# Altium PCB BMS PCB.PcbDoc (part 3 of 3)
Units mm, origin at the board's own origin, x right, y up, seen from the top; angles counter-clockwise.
Board outline 105 x 42 mm, 6 copper layers (TOP, GND TOP, IN, GND IN, GND BOT, BOT), stack 1.517 mm thick; 241 components, 153 nets, 670 pads, 889 vias.
Unrouted connection lines stored in the file: 76.
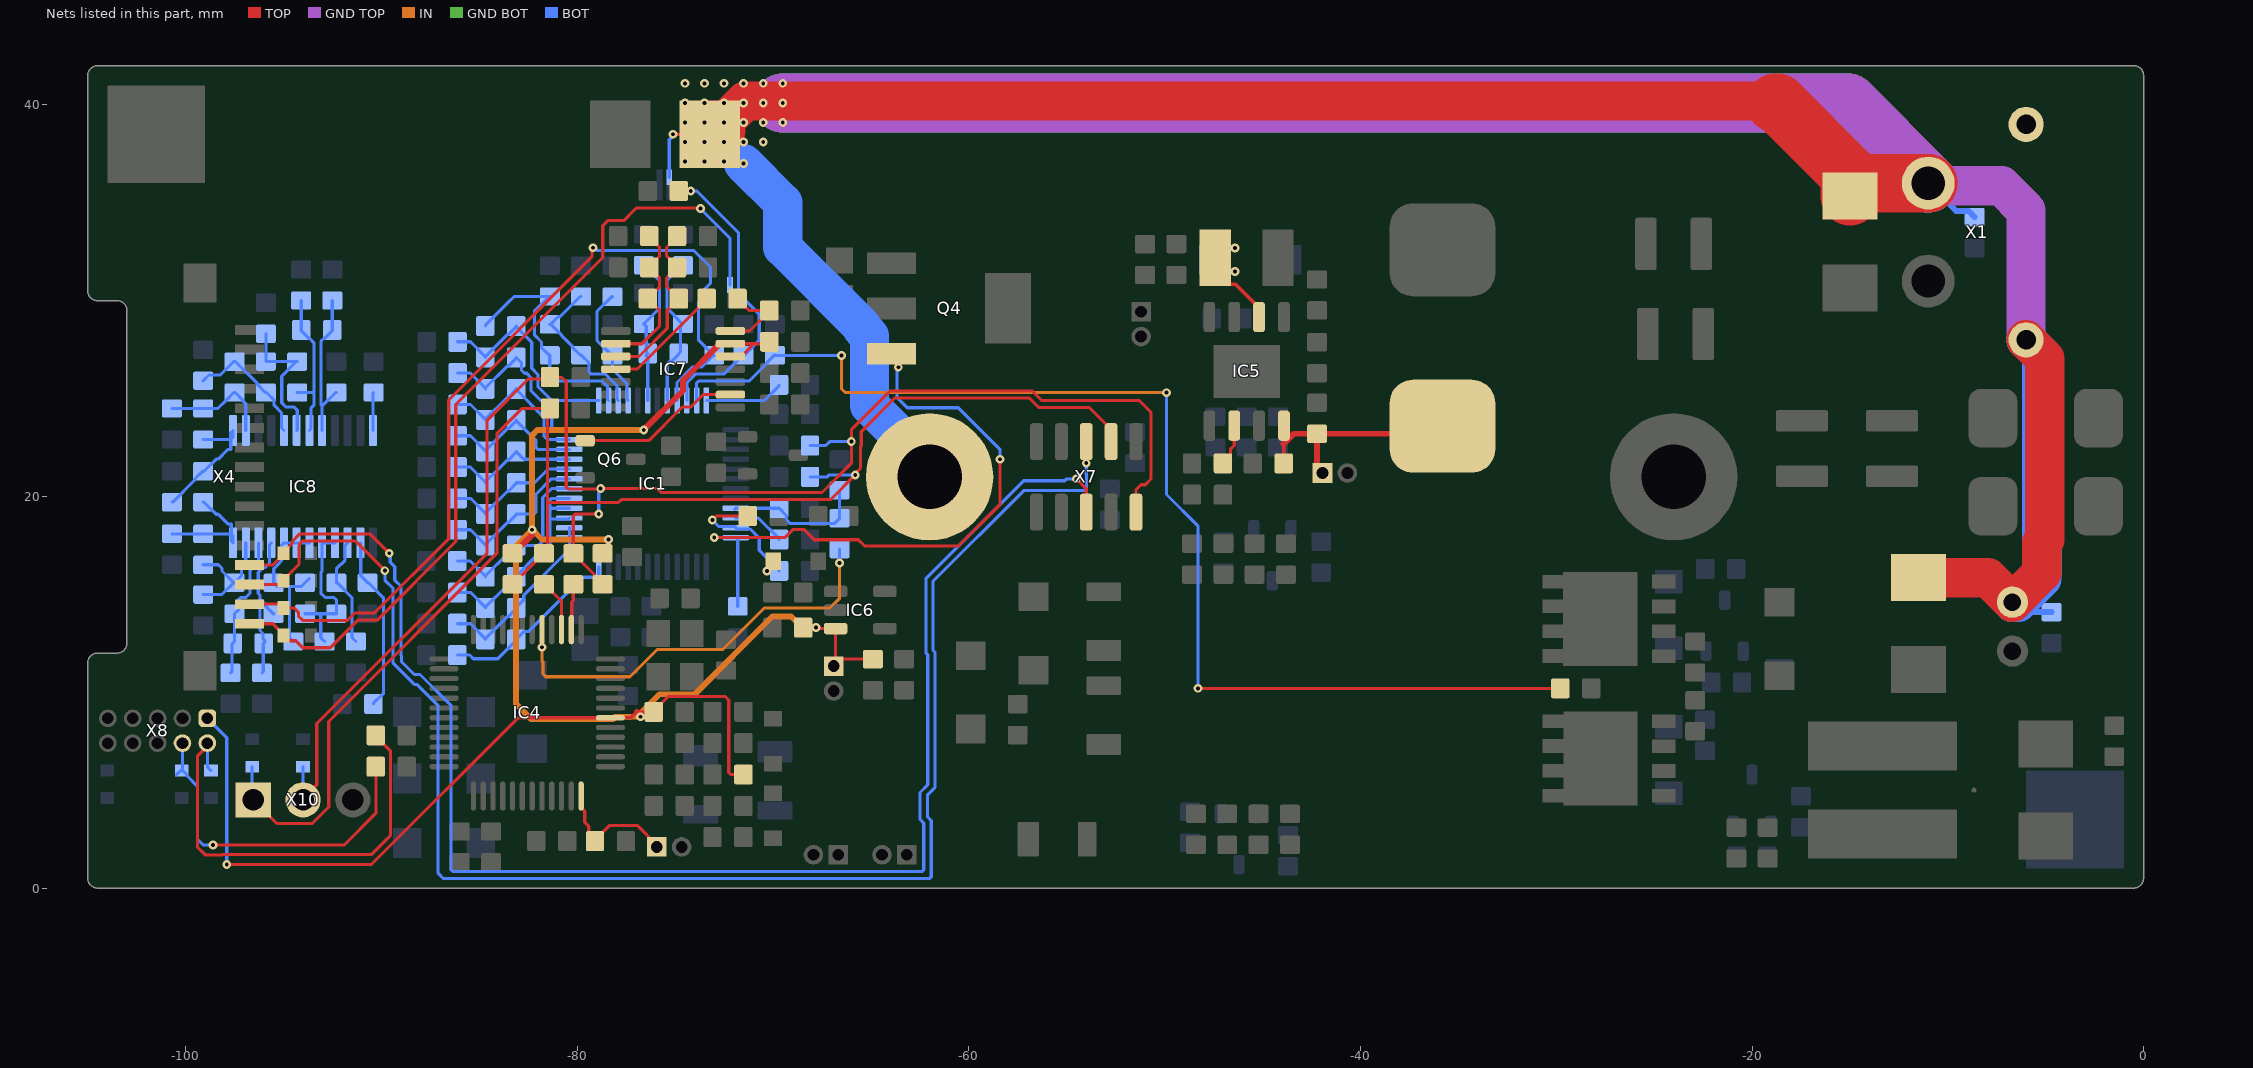
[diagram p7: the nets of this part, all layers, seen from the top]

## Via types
v1: diameter 0.45, hole 0.2, TOP to BOT, tented both sides, 886 vias
v2: diameter 0.45/0.45/0.45/0.45/0.45/0 (per signal layer), hole 0.2, TOP to BOT, tented both sides, 3 vias

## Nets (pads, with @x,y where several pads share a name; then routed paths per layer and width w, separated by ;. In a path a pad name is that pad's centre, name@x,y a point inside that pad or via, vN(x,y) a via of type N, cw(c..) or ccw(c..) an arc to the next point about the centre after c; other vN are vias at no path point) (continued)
PACK-: C38.1 C39.1 D27.A D28.A MH2.1 NT2.1 R1.2 X1.- X1.CASE X2.2 | length 325.7
  TOP w0.16: v1(-75.1,38.5) R1.2@-73.228,38.5
  TOP w0.3: D27.A@-16.25,34.3 -15,35.55 D27.A@-14.8,35.55 ; D28.A@-11.7,15.85 D28.A@-11.5,15.85
  TOP w2: R1.2@-72.893,38.728 -71.421,40.2 -18.9,40.2 -18.8,40.1 ; D28.A@-11.5,15.85 -7.95,15.85 X2.2@-6.7,14.6 -5.2,16.1 -5.2,17.636 -5.05,17.786 -5.05,27.05 X1.CASE@-6,28
  TOP w3: R1.2@-73.228,38.5 -73.228,38.678 -73.178,38.728 R1.2@-72.893,38.728 ; -18.8,40.1 -18.7,40.1 -15,36.4 D27.A@-15,35.35 -14.35,36 X1.-@-11,36
  GND TOP w2: X1.-@-11,36 -10.866,35.866 -7.266,35.866 -6,34.6 X1.CASE@-6,28
  GND TOP w3: v1(-69.5,40.1) -15.1,40.1 X1.-@-11,36
  GND BOT w3: v1(-69.5,40.1) -15.1,40.1 X1.-@-11,36
  BOT w0.16: NT2.1@-75.3,36.3 -75.3,38.222 -75.1,38.422 v1(-75.1,38.5)
  BOT w0.3: X1.-@-11,36 -9.585,34.585 -8.945,34.585 C38.1@-8.625,34.265 ; X2.2@-6.417,14.6 -6.348,14.6 -5.838,14.09 C39.1@-4.7,14.09
  BOT w2: v1(-73.5,38.1) -73.4,38.1 -73,38.5 v1@-72.5,38 ; v1(-71.5,37) -69.5,35 -69.5,32.727 -65.449,28.676 -65.449,28.578 -65.075,28.203 -65.075,24.659 -62,21.584 MH2.1@-62,21 ; X2.2@-6.7,14.6 -6.417,14.6 -5.2,15.817 -5.2,27.2 X1.CASE@-6,28
  BOT w3: v1(-69.5,40.1) -15.1,40.1 X1.-@-11,36
  other v1: -74.5,37.1 -73.5,37.1 -72.5,37.1 -74.5,38.1 -72.5,38.1 -71.5,38.1 -70.5,38.1 -74.5,39.1 -73.5,39.1 -72.5,39.1 -71.5,39.1 -70.5,39.1 -69.5,39.1 -74.5,40.1 -73.5,40.1 -72.5,40.1 -71.5,40.1 -70.5,40.1 -74.5,41.1 -73.5,41.1 -72.5,41.1 -71.5,41.1 -70.5,41.1 -69.5,41.1
PGOOD: D30.K IC5.6 | length 2.2
  TOP w0.16: D30.K@-47.02,21.69 -46.639,22.071 -46.639,22.409 -46.445,22.603 IC5.6@-46.445,23.618
REG1: C15.2 D6.A D43.A IC1.35 | length 6.8
  TOP w0.16: v1(-73.1,18.8) -72.9,19 D43.A@-71.29,19
  BOT w0.16: v1(-73.1,18.8) -72.76,18.46 -71.96,18.46 IC1.35@-71.9,18.4 -71.84,18.34 -71.17,18.34 -70.7,17.87 -70.7,17.25 -69.69,16.24 C15.2@-69.69,16.2
  other v1: -70.3,16.2
REG2: C14.2 IC1.34 | length 2.7
  BOT w0.16: IC1.34@-71.9,18.9 -70.75,18.9 -69.69,17.84 C14.2@-69.69,17.8
REG18: C24.2 IC1.24 | length 4.1
  BOT w0.16: IC1.24@-73.4,24.9 -70.443,24.899 -69.69,25.652 C24.2@-69.69,25.7
REG25: C48.2 IC7.7 R76.2 | length 4.3
  TOP w0.16: IC7.7@-72.175,28.45 -71.2,28.45 -70.19,29.46 C48.2@-70.19,29.5 -71.21,29.5 -71.389,29.679 -71.421,29.679 -71.81,30.068 R76.2@-71.81,30.1
REGIN: C12.2 IC1.36 Q4.E | length 32.2
  TOP w0.16: v1(-73,17.9) -69.4,17.9 -68.995,18.305 -68.405,18.305 -67.89,17.79 -65.642,17.79 -65.322,17.47 -60.538,17.47 -58.4,19.608 v1(-58.4,21.9) ; Q4.E@-63.94,27.3 -63.6,26.96 v1(-63.6,26.6)
  BOT w0.16: v1(-73,17.9) IC1.36@-71.9,17.9 -71.86,17.9 -71.8,17.84 C12.2@-71.8,14.39 ; v1(-63.6,26.6) -63.655,26.545 -63.655,26.38 -63.675,26.361 -63.675,25.069 -63.135,24.53 -60.538,24.53 -58.4,22.392 v1(-58.4,21.9)
RST/SHUT: IC4.17 R32.2 | length 21.7
  TOP w0.16: v1(-81.8,12.3) IC4.17@-81.8,13.2
  IN w0.16: v1(-81.8,12.3) -81.8,11.608 -81.74,11.548 -81.74,10.934 -81.601,10.795 -77.305,10.795 -75.915,12.185 -72.565,12.185 -70.445,14.305 -67.095,14.305 -66.6,14.8 v1(-66.6,16.6)
  BOT w0.16: v1(-66.6,16.6) R32.2@-66.6,17.31
"RST/SHUT BMS": C25.2 IC1.33 R32.1 R34.2 | length 7.4
  BOT w0.16: IC1.33@-71.96,19.34 IC1.33@-71.9,19.4 C25.2@-69.69,19.4 -69.309,19.019 -69.309,18.802 -69.116,18.61 -66.88,18.61 R32.1@-66.6,18.89 R34.2@-66.6,20.31
"SCL MCU": IC4.14 R47.2 | length 2.4
  TOP w0.16: IC4.14@-80.3,13.2 -80.279,13.221 -80.279,14.61 -80.201,14.689 R47.2@-80.2,15.51
SCLt: D5.K R29.2 R45.1 R47.1 R73.2 X7.9 X10.2 | length 84.1
  TOP w0.16: X10.2@-94,4.5 -94,4.58 -93.3,5.28 -93.3,8.406 -84.6,17.106 -84.6,23.9 -82.5,26 -81.49,26 R73.2@-81.39,26.1 -81.364,26.074 -80.774,26.074 -80.56,25.86 -80.56,20.472 -80.466,20.379 -78.821,20.379 v1(-78.8,20.4) -75.911,20.4 -75.711,20.2 -67.5,20.2 -66,21.7 v1(-66,22.8) -66,23.4 -64.01,25.39 -56.773,25.39 -56.283,24.9 -51.286,24.9 -50.7,24.314 -50.7,21.314 -50.695,21.309 -50.695,20.891 -50.991,20.595 -51.205,20.595 -51.46,20.34 X7.9@-51.46,19.2 ; R47.1@-80.56,17.45 R47.1@-80.2,17.09 -80.2,19.006 -80.106,19.1 v1(-78.9,19.1) ; R47.1@-80.168,17.09 -79.779,16.701 -79.779,16.669 -79.121,16.011 -79.121,15.899 -78.732,15.51 R45.1@-78.7,15.51
  BOT w0.16: X10.2@-94,4.5 D5.K@-94,6.2 ; v1(-78.9,19.1) -78.9,20.222 -78.8,20.322 v1(-78.8,20.4) ; R29.2@-68.11,22.6 -67.3,22.6 -67.1,22.8 v1(-66,22.8)
"SDA MCU": IC4.15 R48.2 | length 2.7
  TOP w0.16: R48.2@-81.7,15.51 -81.66,15.51 -80.8,14.65 IC4.15@-80.8,13.2
SDAt: D4.K R27.2 R46.1 R48.1 R71.2 X7.8 X10.1 | length 77.9
  TOP w0.16: X10.1@-96.54,4.5 -95.34,3.3 -93.531,3.3 -92.688,4.143 -92.688,8.509 -84.1,17.097 -84.1,23.2 -82.8,24.5 R71.2@-81.39,24.5 -81.525,24.365 -81.525,19.7 ; R46.1@-83.3,15.51 -83.268,15.51 -82.879,15.899 -82.879,15.931 -82.121,16.689 -82.121,16.701 -81.733,17.09 R48.1@-81.7,17.09 -81.7,17.3 -81.525,17.475 -81.525,19.7 ; X7.8@-52.73,22.8 -52.73,23.42 -53.85,24.54 -56.432,24.54 -56.922,25.03 -63.778,25.03 -65.495,23.313 -65.495,22.591 -65.53,22.556 -65.53,21.448 -65.8,21.178 v1(-65.8,21.1) -67.06,19.84 -77.746,19.84 -77.891,19.695 -78.309,19.695 -78.314,19.7 -81.525,19.7
  BOT w0.16: D4.K@-96.6,6.2 -96.6,4.56 X10.1@-96.54,4.5 ; R27.2@-68.11,21 -67.231,21 -67.131,21.1 v1(-65.8,21.1)
SRN: C28.2 C30.2 IC1.20 R37.2 | length 8
  BOT w0.16: IC1.20@-75.4,24.9 -75.4,26.776 -75.298,26.879 -75.199,26.879 -74.81,27.267 C28.2@-74.81,27.3 -74.725,27.385 -74.725,28.685 C30.2@-74.6,28.81 -74.632,28.81 -75.021,29.199 -75.021,29.231 -75.409,29.619 -75.409,31.044 -75.315,31.137 -75.31,31.137 -74.647,31.8 R37.2@-74.6,31.8
"SRN FG": C49.2 C51.2 IC7.10 R75.2 | length 9.2
  TOP w0.16: IC7.10@-78.025,27.15 -76.841,27.15 -75.4,28.591 -75.4,29.51 -75.231,29.679 -75.199,29.679 -74.81,30.068 -74.81,30.132 -75.199,30.521 -75.231,30.521 -75.44,30.73 -75.44,31.16 -75.321,31.279 -75.289,31.279 -74.9,31.668 -74.9,31.748 -75.44,32.288 -75.44,32.712 -74.9,33.252 R75.2@-74.9,33.3
SRP: C28.1 C29.1 IC1.18 R36.2 | length 7.7
  BOT w0.16: R36.2@-76.6,31.81 -75.8,31.01 -75.8,29.61 C29.1@-76.6,28.81 -76.475,28.685 -76.475,27.385 C28.1@-76.39,27.3 -76.49,27.2 -76.4,27.11 IC1.18@-76.4,24.9
"SRP FG": C49.1 C50.1 IC7.9 R74.2 | length 8.4
  TOP w0.16: IC7.9@-78.025,27.8 -76.7,27.8 -75.8,28.7 -75.8,29.51 -75.969,29.679 -76.001,29.679 -76.39,30.068 -76.39,30.132 -76.001,30.521 -75.969,30.521 -75.8,30.69 -75.8,31.176 -75.902,31.279 -75.931,31.279 C50.1@-76.32,31.668 ; C50.1@-76.32,31.7 -76.32,31.748 -75.8,32.268 -75.8,32.732 -76.32,33.252 R74.2@-76.32,33.3
"SW 5V1": C40.2 IC5.8 L2.1 R62.1 X11.1 | length 13.5
  TOP w0.16: -43.92,22.68 C40.2@-43.92,21.73 ; IC5.8@-43.905,23.618 -43.905,22.695 C40.2@-43.905,21.745 ; C40.2@-43.92,21.73 C40.2@-43.92,21.69 -43.905,21.705 C40.2@-43.905,21.745 ; C40.2@-43.92,21.73 C40.2@-43.905,21.745
  TOP w0.3: -43.92,22.68 -43.905,22.695 -43.4,23.2 R62.1@-42.21,23.2 ; X11.1@-41.935,21.2 -42.21,21.475 R62.1@-42.21,23.2 ; L2.1@-35.81,23.59 -36.2,23.2 R62.1@-42.21,23.2
SWCLK: D2.K R50.2 X8.4 | length 17.9
  TOP w0.16: v1(-98.6,2.2) -91.9,2.2 -90.28,3.82 -90.28,6.19 R50.2@-90.29,6.2
  BOT w0.16: D2.K@-100.47,5.78 -100.25,6 D2.K@-100.2,6 ; X8.4@-100.16,7.4 -100.16,6.04 D2.K@-100.2,6 ; v1(-98.6,2.2) -99.1,2.2 -99.4,2.5 -99.4,5.2 -99.93,5.73 -99.93,5.78 -100.15,6 D2.K@-100.2,6
SWDIO: D1.K R49.2 X8.2 | length 23
  TOP w0.16: X8.2@-98.89,7.4 -98.89,7.246 -99.4,6.736 -99.4,2.1 -98.995,1.695 -98.119,1.695 -98.109,1.705 -90.515,1.705 -89.54,2.68 -89.54,7.01 -90.29,7.76 R49.2@-90.29,7.8
  BOT w0.16: X8.2@-98.814,7.476 X8.2@-98.89,7.4 -98.89,6.19 D1.K@-98.7,6
TS1: C20.2 D35.A IC1.21 X4.15 | length 45.1
  TOP w0.16: X4.15@-96.737,14.5 -95.2,14.5 D35.A@-95,14.3 -94.46,14.3 -94.238,14.078 -94.238,13.892 -94.016,13.67 -91.73,13.67 -91.355,14.045 -90.364,14.045 -86.56,17.849 -86.56,24.926 -79.251,32.235 -79.251,32.649 v1(-79.2,32.7)
  BOT w0.16: v1(-79.2,32.7) -79.122,32.7 -78.981,32.56 -74.039,32.56 -73.195,31.716 -73.195,30.891 -73.6,30.486 -73.6,30.1 -73.8,29.9 -73.8,27.97 C20.2@-73.04,27.21 ; IC1.21@-74.9,24.9 -74.9,25.818 -74.098,26.62 -73.638,26.62 -73.048,27.21 C20.2@-73.04,27.21 ; C20.2@-73,27.21 C20.2@-73.04,27.21
"TS1+ C": D33.A X4.13 X7.5 | length 77.1
  TOP w0.16: X4.13@-96.737,16.5 -95.55,16.5 -95,17.05 D33.A@-95,17.1 -95,17.15 -94.54,17.61 -94.54,17.715 -94.165,18.09 -90.59,18.09 v1(-89.6,17.1) ; v1(-54.5,20.9) -54,20.4 X7.5@-54,19.2
  BOT w0.16: v1(-89.6,17.1) -89.545,17.045 -89.545,16.642 -89.32,16.417 -89.32,15.729 -89,15.409 -89,11.879 -88.977,11.857 -88.977,11.574 -88.314,10.91 -88.031,10.91 -86.44,9.319 -86.44,0.934 -86.346,0.84 -62.394,0.84 -62.3,0.934 -62.3,3.317 -62.495,3.512 -62.495,4.88 -62.095,5.28 -62.095,11.909 -62.195,12.009 -62.195,15.805 -57.2,20.8 -55.514,20.8 -55.509,20.805 -55.091,20.805 -54.996,20.9 v1(-54.5,20.9)
"TS1- C": D34.A X4.14 X7.6 | length 78.6
  TOP w0.16: X4.14@-96.737,15.5 -95.2,15.5 D34.A@-95,15.7 -95,15.75 -94.205,16.545 -94.205,17.436 -94.18,17.461 -94.18,17.566 -94.016,17.73 -91.33,17.73 -89.825,16.225 v1(-89.825,16.208) ; v1(-54,21.7) X7.6@-54,22.8
  BOT w0.16: v1(-89.825,16.208) -89.825,15.725 -89.4,15.3 -89.4,11.487 -88.314,10.402 -88.186,10.402 -87.1,9.316 -87.1,0.754 -86.826,0.48 -62.011,0.48 -61.917,0.574 -61.917,3.443 -62.1,3.626 -62.1,3.886 -62.105,3.891 -62.105,4.309 -62.1,4.314 -62.1,4.764 -61.735,5.129 -61.735,12.058 -61.835,12.158 -61.835,15.656 -57.191,20.3 -54.094,20.3 -53.995,20.399 -53.995,21.109 -54,21.114 v1(-54,21.7)
TS2: C53.2 IC1.22 R78.2 | length 15.4
  TOP w0.16: R78.2@-74.81,35.6 v1(-74.2,35.6)
  BOT w0.16: IC1.22@-74.4,24.9 -74.394,24.906 -74.394,25.815 -73.949,26.26 -72.49,26.26 -71.54,27.21 C53.2@-71.5,27.21 -71.46,27.21 -70.7,27.97 -70.7,29.311 -71.77,30.381 -71.77,33.484 -73.886,35.6 v1(-74.2,35.6)
"TS2- C": D36.A NT3.1 X4.16 | length 42.5
  TOP w0.16: X4.16@-96.737,13.5 -95.55,13.5 -95,12.95 D36.A@-95,12.9 -95,12.85 -94.78,12.63 -94.376,12.63 -94.016,12.27 -92.621,12.27 -91.206,13.685 -90.215,13.685 -86.2,17.7 -86.2,24.7 -78.695,32.205 -78.695,33.826 -78.431,34.09 -77.619,34.09 -76.969,34.74 -74.96,34.74 -73.74,34.74 v1(-73.7,34.7)
  BOT w0.16: v1(-73.7,34.7) -72.2,33.2 NT3.1@-72.2,30.8
TS3: C54.2 IC1.23 R77.2 | length 61.6
  TOP w0.16: v1(-48.3,10.2) R77.2@-29.79,10.2
  IN w0.16: v1(-66.5,27.2) -66.5,25.5 -66.3,25.3 v1(-49.9,25.3)
  BOT w0.16: IC1.23@-73.9,24.9 -73.9,25.8 -73.8,25.9 -71.21,25.9 -70.321,26.789 -70.321,26.821 -69.932,27.21 C54.2@-69.9,27.21 -69.89,27.2 v1(-66.5,27.2) ; v1(-49.9,25.3) -49.9,20.1 -48.3,18.5 v1(-48.3,10.2)
"TS FG": IC7.11 R76.1 | length 6.1
  TOP w0.16: IC7.11@-78.025,26.5 -78.02,26.505 -76.945,26.505 -73.39,30.06 R76.1@-73.39,30.1
"TS+ BQ": IC8.24 R109.2 | length 2
  BOT w0.16: IC8.24@-90.425,23.37 -90.425,25.285 R109.2@-90.4,25.31
V1: C67.1 C68.2 IC8.20 R92.2 | length 7.9
  BOT w0.16: IC8.20@-93.025,23.37 -93.025,24.625 ; R92.2@-92.5,30.01 -92.51,30 C67.1@-92.51,28.5 -92.51,28.468 -92.899,28.079 -92.931,28.079 -93.09,27.92 -93.09,24.69 -93.025,24.625 ; C68.2@-92.3,25.31 -92.34,25.31 -93.025,24.625
V2: C66.1 C67.2 IC8.19 R91.2 | length 7.9
  BOT w0.16: C66.1@-94.3,25.31 -93.46,25.31 -93.45,25.3 ; R91.2@-94.1,30.01 -94.09,30 C67.2@-94.09,28.5 ; C67.2@-94.09,28.496 -94.09,28.468 -93.701,28.079 -93.673,28.079 -93.45,27.856 -93.45,25.3 ; IC8.19@-93.675,23.37 -93.6,23.445 -93.6,24.5 -93.45,24.65 -93.45,25.3
V3: C65.1 C66.2 IC8.18 R90.2 | length 7.4
  BOT w0.16: R90.2@-95.9,28.31 C65.1@-95.9,26.89 C66.2@-94.34,26.89 ; IC8.18@-94.325,23.37 -94.3,23.395 -94.3,24.4 -94.46,24.56 -94.871,24.56 -95.09,24.779 -95.09,26.14 C66.2@-94.34,26.89 ; C66.2@-94.3,26.89 C66.2@-94.34,26.89
V4: C64.1 C65.2 IC8.17 R89.2 | length 6.6
  BOT w0.16: R89.2@-99.1,25.91 -98.804,26.206 -98.224,26.206 -97.54,26.89 C64.1@-97.5,26.89 -97.46,26.89 -96.321,25.751 -96.321,25.699 -95.932,25.31 C65.2@-95.9,25.31 -95.868,25.31 -95.479,24.921 -95.479,24.659 -95.1,24.28 -95.1,23.495 IC8.17@-94.975,23.37
V5: C63.1 C64.2 IC8.14 R88.2 | length 5.7
  BOT w0.16: R88.2@-100.7,24.49 C63.1@-99.1,24.49 -98.35,24.49 -97.921,24.919 -97.921,24.921 -97.532,25.31 C64.2@-97.5,25.31 -97.468,25.31 -97.079,24.921 -97.079,24.889 -96.925,24.735 IC8.14@-96.925,23.37
V6: C62.1 C63.2 IC8.13 R87.2 | length 7.1
  BOT w0.16: R87.2@-100.7,19.71 -100.66,19.71 -99.521,20.849 -99.521,20.901 -99.132,21.29 C62.1@-99.1,21.29 -99.06,21.29 -98.441,21.909 -98.341,21.909 -97.85,22.4 -97.694,22.4 IC8.13@-97.694,22.916 ; C63.2@-99.1,22.91 -97.7,22.91 IC8.13@-97.694,22.916 ; IC8.13@-97.694,22.916 -97.694,23.251 IC8.13@-97.575,23.37 -97.575,23.035 IC8.13@-97.694,22.916
V7: C61.1 C62.2 IC8.12 R86.2 | length 6.4
  BOT w0.16: R86.2@-100.7,18.09 C61.1@-99.1,18.09 -97.7,18.09 IC8.12@-97.669,18.059 ; C62.2@-99.1,19.71 -99.06,19.71 -98.441,19.091 -98.341,19.091 -97.85,18.6 -97.669,18.6 IC8.12@-97.669,18.059 ; IC8.12@-97.669,18.059 -97.575,17.965 IC8.12@-97.575,17.63 -97.669,17.724 IC8.12@-97.669,18.059
V8: C60.1 C61.2 IC8.11 R85.2 | length 6.2
  BOT w0.16: R85.2@-99.1,14.99 -98.148,14.99 -97.548,15.59 C60.1@-97.532,15.59 ; C61.2@-99.1,16.51 -98.32,16.51 -98.139,16.329 -98.139,16.196 C60.1@-97.532,15.59 ; IC8.11@-96.925,17.63 -96.925,16.529 -97.154,16.3 -97.154,15.936 C60.1@-97.5,15.59 C60.1@-97.532,15.59
V9: C59.1 C60.2 IC8.10 R84.2 | length 7.4
  BOT w0.16: R84.2@-97.7,10.99 -97.625,11.065 -97.625,12.465 C59.1@-97.59,12.5 -97.5,12.59 C60.2@-97.5,14.01 -97.29,14.22 -97.29,14.746 -97.196,14.84 -96.929,14.84 -96.71,15.059 -96.71,16.21 -96.275,16.645 IC8.10@-96.275,17.63
V10: C58.1 C59.2 IC8.9 R83.2 | length 8.2
  BOT w0.16: R83.2@-96.1,10.99 -96.035,11.055 -96.035,12.475 C59.2@-96.01,12.5 -95.96,12.55 -95.96,12.65 -96.051,12.741 -96.051,13.003 -96.2,13.152 -96.2,14.77 ; IC8.9@-95.625,17.63 -95.706,17.549 -95.706,16.605 -95.948,16.363 -96.048,16.363 -96.29,16.121 -96.29,15.059 -96.2,14.969 -96.2,14.77 ; C58.1@-95.5,14.01 -95.532,14.01 -95.989,14.467 -95.989,14.559 -96.2,14.77
V11: C57.1 C58.2 IC8.6 IC8.7 IC8.8 R82.2 | length 8.5
  BOT w0.16: R82.2@-94.5,12.59 -94.7,12.79 -94.7,15.406 ; C57.1@-93.675,15.815 C57.1@-93.9,15.59 -94.084,15.406 -94.7,15.406 ; IC8.6@-93.675,17.63 IC8.7@-94.325,17.63 IC8.8@-94.975,17.63 -95.1,17.505 -95.1,16.714 -95.326,16.488 -95.326,16.474 -95.5,16.3 C58.2@-95.5,15.59 -95.316,15.406 -94.7,15.406
V12: C56.1 C57.2 IC8.4 IC8.5 R81.2 | length 8
  BOT w0.16: C57.2@-93.9,14.01 -93.1,14.01 ; R81.2@-92.9,12.59 -93.1,12.79 -93.1,14.01 ; IC8.4@-92.375,17.63 IC8.5@-93.025,17.63 -93.025,16.186 -93.09,16.121 -93.09,15.059 -92.871,14.84 -92.42,14.84 -92.3,14.72 C56.1@-92.3,14.01 -93.1,14.01
V13: C56.2 IC8.3 R80.2 | length 5.7
  BOT w0.16: IC8.3@-91.725,17.63 -91.85,17.505 -91.85,16.75 -92.3,16.3 C56.2@-92.3,15.59 -92.26,15.59 -91.5,14.83 -91.5,12.79 R80.2@-91.3,12.59
VC0: C27.2 IC1.16 R35.2 | length 6.3
  BOT w0.16: R35.2@-78.2,30.2 -78.24,30.2 -78.99,29.45 -78.99,27.96 -78.24,27.21 C27.2@-78.2,27.21 -78.2,26.5 -77.46,25.76 -77.46,24.96 IC1.16@-77.4,24.9
VC1: C23.1 C26.2 IC1.15 R33.2 | length 8
  BOT w0.16: C23.1@-81.4,28.79 C23.1@-81.36,28.79 ; R33.2@-79.8,30.21 -79.84,30.21 -80.879,29.171 -80.979,29.171 C23.1@-81.36,28.79 ; IC1.15@-77.9,24.9 -77.96,24.96 -77.96,25.639 -78.581,26.26 -79.306,26.26 -79.4,26.354 -79.4,26.821 -79.789,27.21 C26.2@-79.8,27.21 -79.832,27.21 -80.221,27.599 -80.221,27.651 C23.1@-81.36,28.79
VC2: C22.1 C23.2 IC1.14 R30.2 | length 12.5
  BOT w0.16: C22.1@-84.69,28.7 -84.69,28.74 -83.516,29.914 -83.22,30.21 R30.2@-81.44,30.21 ; R30.2@-81.4,30.21 R30.2@-81.44,30.21 ; IC1.14@-78.4,24.9 -78.46,24.96 -78.46,25.63 -78.73,25.9 -81.1,25.9 -81.4,26.2 C23.2@-81.4,27.21 -81.432,27.21 -81.821,27.599 -81.821,27.89 -82.19,28.259 -82.19,29.46 R30.2@-81.44,30.21
VC3: C21.1 C22.2 IC1.13 R28.2 | length 10.9
  BOT w0.16: R28.2@-86.11,27.9 -85.45,27.9 C21.1@-84.69,27.14 ; C21.1@-84.69,27.1 C21.1@-84.69,27.14 ; C22.2@-83.11,28.7 C22.2@-83.11,28.667 ; IC1.13@-78.9,24.9 -81.3,24.9 -82,25.6 -82,26.22 -82.32,26.54 -82.32,27.87 -83.11,28.66 C22.2@-83.11,28.667 ; C21.1@-84.69,27.14 -83.551,28.279 -83.499,28.279 C22.2@-83.11,28.667
VC4: C19.1 C21.2 IC1.12 R26.2 | length 9.4
  BOT w0.16: R26.2@-86.11,26.3 -85.45,26.3 C19.1@-84.69,25.54 ; C19.1@-84.69,25.5 C19.1@-84.69,25.54 ; IC1.12@-80.4,23.4 -80.46,23.46 -81.266,23.46 -81.3,23.494 -81.3,24.34 -82.36,25.4 -82.36,26.071 -82.579,26.29 -82.69,26.29 -82.844,26.444 -82.844,26.834 C21.2@-83.11,27.1 -83.11,27.067 -83.499,26.679 -83.551,26.679 C19.1@-84.69,25.54
VC5: C18.1 C19.2 IC1.11 R25.2 | length 8.4
  BOT w0.16: R25.2@-86.11,24.7 -85.45,24.7 C18.1@-84.69,23.94 ; C18.1@-84.69,23.9 C18.1@-84.69,23.94 ; C19.2@-83.11,25.5 C19.2@-83.11,25.467 ; IC1.11@-80.4,22.9 -81.5,22.9 -81.7,23.1 -81.7,24.05 -83.11,25.46 C19.2@-83.11,25.467 ; C18.1@-84.69,23.94 -83.551,25.079 -83.499,25.079 C19.2@-83.11,25.467
VC6: C17.1 C18.2 IC1.10 R24.2 | length 7.6
  BOT w0.16: R24.2@-86.11,23.1 -85.45,23.1 C17.1@-84.69,22.34 ; C17.1@-84.69,22.3 C17.1@-84.69,22.34 ; C18.2@-83.11,23.9 C18.2@-83.11,23.867 ; IC1.10@-80.4,22.4 -82.006,22.4 -82.1,22.494 -82.1,22.85 -83.11,23.86 C18.2@-83.11,23.867 ; C17.1@-84.69,22.34 -83.551,23.479 -83.499,23.479 C18.2@-83.11,23.867
VC7: C16.1 C17.2 IC1.9 R23.2 | length 6.9
  BOT w0.16: R23.2@-86.11,21.5 -85.45,21.5 C16.1@-84.69,20.74 ; C16.1@-84.69,20.7 C16.1@-84.69,20.74 ; C17.2@-83.11,22.3 C17.2@-83.11,22.289 ; IC1.9@-80.4,21.9 -82.721,21.9 C17.2@-83.11,22.289 ; C16.1@-84.69,20.74 -83.551,21.879 -83.499,21.879 -83.11,22.267 C17.2@-83.11,22.289
VC8: C11.1 C16.2 IC1.8 R22.2 | length 7
  BOT w0.16: R22.2@-86.11,19.9 -85.45,19.9 C11.1@-84.69,19.14 ; C11.1@-84.69,19.1 C11.1@-84.69,19.14 ; IC1.8@-80.4,21.4 -81.478,21.4 -82.178,20.7 C16.2@-83.11,20.7 -83.11,20.667 -83.499,20.279 -83.551,20.279 C11.1@-84.69,19.14
VC9: C10.1 C11.2 IC1.7 R21.2 | length 8
  BOT w0.16: R21.2@-86.11,18.3 -85.45,18.3 C10.1@-84.69,17.54 ; C10.1@-84.69,17.5 C10.1@-84.69,17.54 ; IC1.7@-80.4,20.9 -81.318,20.9 -82.12,20.098 -82.12,19.194 -82.214,19.1 C11.2@-83.11,19.1 -83.11,19.067 -83.499,18.679 -83.551,18.679 C10.1@-84.69,17.54
VC10: C8.1 C10.2 IC1.6 R20.2 | length 9.3
  BOT w0.16: R20.2@-86.12,16.7 -85.45,16.7 C8.1@-84.69,15.94 ; C8.1@-84.69,15.9 C8.1@-84.69,15.94 ; IC1.6@-80.4,20.4 -81.309,20.4 -81.76,19.949 -81.76,17.7 -81.96,17.5 C10.2@-83.11,17.5 -83.11,17.467 -83.499,17.079 -83.551,17.079 C8.1@-84.69,15.94
VC11: C6.1 C8.2 IC1.3 IC1.4 IC1.5 R18.2 | length 11.8
  BOT w0.16: R18.2@-86.12,15.1 -85.45,15.1 C6.1@-84.69,14.34 ; C6.1@-84.69,14.3 C6.1@-84.69,14.34 ; IC1.3@-80.4,18.9 -80.46,18.84 -81.36,18.84 -81.4,18.8 ; IC1.4@-80.4,19.4 -81.3,19.4 -81.4,19.3 ; IC1.5@-80.4,19.9 -81.3,19.9 -81.4,19.8 -81.4,19.3 ; C6.1@-84.69,14.34 -83.551,15.479 -83.499,15.479 -83.11,15.867 -83.11,15.94 -82.112,16.938 -82.013,16.938 -81.4,17.551 -81.4,18.8 ; -81.4,18.8 -81.4,19.3
VC12: C5.1 C6.2 IC1.1 IC1.2 R14.2 | length 9.3
  BOT w0.16: R14.2@-86.12,13.5 -85.45,13.5 C5.1@-84.69,12.74 ; C5.1@-84.69,12.7 C5.1@-84.69,12.74 ; IC1.2@-80.4,18.4 IC1.1@-80.4,17.9 -80.4,17.289 -82.729,14.96 -82.729,14.721 -83.11,14.34 C6.2@-83.11,14.3 -83.11,14.267 -83.499,13.879 -83.551,13.879 C5.1@-84.69,12.74
VC13: C5.2 IC1.48 R10.2 | length 9.5
  BOT w0.16: R10.2@-86.12,11.9 -85.494,11.9 -85.304,11.71 -84.06,11.71 -83.11,12.66 -83.11,12.709 -82.721,13.098 -82.502,13.098 -79.725,15.875 -78.96,15.875 -78.9,15.935 IC1.48@-78.9,16.4
VCORE: C36.2 IC4.48 X14.1 | length 6.5
  TOP w0.16: IC4.48@-79.8,4.7 -79.8,4.115 -79.749,4.064 -79.743,4.064 -79.615,3.936 -79.615,3.357 -79.408,3.15 -79.408,2.718 C36.2@-79.09,2.4 -79.09,2.44 -78.33,3.2 -76.935,3.2 X14.1@-75.935,2.2
VDD: C35.2 C46.2 C47.2 D31.A IC4.6 IC6.3 IC7.5 IC7.6 R45.2 R46.2 R52.2 X8.1 X13.1 | length 102.6
  TOP w0.16: v1(-97.9,1.2) -90.511,1.2 -83.016,8.695 -78.305,8.695 IC4.6@-78.3,8.7 -77.258,8.7 -76.958,9 C35.2@-76.09,9 -76.09,9.04 -75.34,9.79 -72.449,9.79 -72.26,9.601 -72.26,5.894 -72.166,5.8 R52.2@-71.51,5.8 ; IC7.5@-72.175,27.15 -71.625,27.15 -71,27.775 -71,27.8 ; IC7.6@-72.175,27.8 -71,27.8 ; C47.2@-70.19,27.9 -70.29,27.8 -71,27.8 ; C46.2@-68.455,13.3 -68.405,13.25 -67.8,13.25 IC6.3@-66.8,13.25 X13.1@-66.8,11.69 ; X13.1@-66.9,11.335 X13.1@-66.8,11.435 ; D31.A@-64.9,11.69 X13.1@-66.545,11.69 ; X13.1@-66.8,11.435 X13.1@-66.8,11.69 ; X13.1@-66.8,11.435 -66.645,11.59 X13.1@-66.545,11.69 ; X13.1@-66.8,11.69 X13.1@-66.545,11.69
  TOP w0.3: R46.2@-83.3,17.09 -83.26,17.09 -82.3,18.05 v1(-82.3,18.3) ; R45.2@-78.7,17.09 -78.429,17.361 -78.429,17.771 v1(-78.4,17.8) ; -76.958,9 -76.958,8.976 -76.77,8.788 v1(-76.77,8.748) ; v1(-76.6,23.4) -74.6,25.4 -74.6,25.925 -72.725,27.8 IC7.6@-72.175,27.8
  IN w0.3: v1(-78.4,17.8) -81.8,17.8 v1(-82.3,18.3) ; v1(-76.6,23.4) -82.024,23.4 -82.3,23.124 v1(-82.3,18.3) ; v1(-67.8,13.3) -68.502,13.3 -69.077,13.875 -70.025,13.875 -74,9.9 -75.8,9.9 -76.77,8.93 v1(-76.77,8.748) -78.063,8.748 -78.186,8.625 -82.349,8.625 -83.135,9.411 -83.135,17.465 v1(-82.3,18.3)
  BOT w0.16: X8.1@-98.89,8.67 -97.9,7.68 v1(-97.9,1.2)
"VDD BQ": C55.2 IC8.2 R79.2 | length 9
  BOT w0.16: IC8.2@-91.075,17.63 -91.055,17.611 -91.055,15.945 C55.2@-90.7,15.59 -90.66,15.59 -89.9,14.83 -89.9,9.924 -90.003,9.821 -90.021,9.821 -90.41,9.432 R79.2@-90.41,9.4
"VEN FG": IC7.2 Q6.G | length 8.4
  TOP w0.16: Q6.G@-79.6,22.85 -76.848,22.85 -76.35,22.85 -74.629,24.571 -74.2,24.571 -73.572,25.2 IC7.2@-72.175,25.2
"VIN 5V1": C43.2 D29.K IC5.2 | length 7.8
  TOP w0.16: C43.2@-48.13,30.818 -47.41,31.538 C43.2@-47.41,31.864
  TOP w0.2: C43.2@-47.41,31.538 -46.71,30.838 -46.376,30.838 -45.175,29.637 IC5.2@-45.175,29.162 ; C43.2@-47.41,31.864 C43.2@-47.41,32.19
  BOT w0.3: v1(-46.41,31.49) -46.905,31.49 -47.485,32.07 -47.485,32.11 -46.905,32.69 v1(-46.41,32.69)
pads on no net: IC1.19 IC1.28 IC1.31 IC1.32 IC1.39 IC1.40 IC4.1 IC4.2 IC4.8 IC4.9 IC4.10 IC4.20 IC4.21 IC4.22 IC4.23 IC4.24 IC4.25 IC4.26 IC4.27 IC4.28 IC4.29 IC4.30 IC4.31 IC4.32 IC4.33 IC4.36 IC4.37 IC4.39 IC4.40 IC4.41 IC4.42 IC4.43 IC4.44 IC4.45 IC8.1 IC8.15 IC8.16 X8.6 X8.8

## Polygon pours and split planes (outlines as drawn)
BAT on BOT "BAT_L06_P092" (solid, pour order 92): -78.5,13.8 -78.5,14.9 -78.1,15.3 -78.1,17.2 -78.6,17.2 -78.6,15.7 -78.8,15.5 -79.8,15.5 -80.4,14.9 -80.4,13.2 -78.8,13.2 -78.7,13.1 -78.7,12.2 -77.1,12.2 -77.1,13.7 -77.2,13.8
CP1 on BOT "CP1_L06_P091" (solid, pour order 91): -77.2,13.8 -77.2,14.9 -77.6,15.3 -77.6,17.2 -78.1,17.2 -78.1,15.3 -78.5,14.9 -78.5,13.8
PACK- on BOT "PACK-_L06_P001" (solid, pour order 1): -74.8,36.5 -71.4,36.5 -69.9,38 -19.9,38 -17.208,35.308 -17.208,33.3 0,33.3 0,42 -74.8,42
GND_BMS on BOT "GND_BMS_L06_P090" (solid, pour order 90): -96,36.5 -79.6,36.5 -76.3,36.5 -76.3,42 -96,42
GND_BMS on BOT "GND_BMS_L06_P085" (solid, pour order 85): -105,33 -96,33 -96,42 -105,42
NetC38_2 on BOT "NETC38_2_L06_P002" (solid, pour order 2): 0,21.7 -3.8,21.7 -3.8,27.4 -5,28.6 -17.3,28.6 -17.3,33.3 0,33.3
NetC39_2 on BOT "NETC39_2_L06_P003" (solid, pour order 3): -4.4,13.3 -7.3,13.3 -8,12.6 -8,9.4 -4.4,9.4
NetC39_2 on BOT "NETC39_2_L06_P004" (solid, pour order 4): -4.4,9.4 0,9.4 0,21.7 -3.8,21.7 -3.8,13.9 -4.4,13.3
BAT+ on BOT "BAT+_L06_P008" (solid, pour order 8): -18,5 -18,9.6 -9.609,17.991 -9.609,28.8 -5,28.8 -5,21.5 0,21.5 0,7.5 -8,7.5 -8,5.015 -8.015,5
"BAT+ C" on BOT "BOT-BAT+ C" (solid, pour order 84): 0,0 0,7.5 -8,7.5 -8.015,7.485 -8.015,5 -18,5 -18,0
SCLt on BOT "SCLT_L06_P080" (solid, pour order 80): -94.9,6.6 -94.9,3.6 -93.1,3.6 -93.1,6.6
SDAt on BOT "SDAT_L06_P078" (solid, pour order 78): -97.5,3.6 -97.5,6.6 -95.6,6.6 -95.6,3.6
SWDIO on BOT "SWDIO_L06_P077" (solid, pour order 77): -99.4,5.5 -99.4,7.9 -98.2,7.9 -98.2,5.5
SWCLK on BOT "SWCLK_L06_P064" (solid, pour order 64): -100.7,5.5 -99.6,5.5 -99.6,7.9 -100.7,7.9
nRST on BOT "NRST_L06_P063" (solid, pour order 63): -104.5,5.6 -103.4,5.6 -103.4,7.9 -104.5,7.9
REG2 on BOT "REG2_L06_P060" (solid, pour order 60): -72.7,18.6 -72.7,19.1 -70.5,19.1 -70,18.6 -69.99,18.61 -69.01,18.61 -69,18.6 -69,17 -70.1,17 -70.4,17.3 -70.4,17.8 -71.2,18.6
REG1 on BOT "REG1_L06_P059" (solid, pour order 59): -71.1,17.866 -71.3,18.1 -72.7,18.1 -72.7,18.6 -71.2,18.6 -70.4,17.8 -70.4,17.3 -70.1,17 -69,17 -69,15.5 -71.1,15.5
REGIN on BOT "REGIN_L06_P023" (solid, pour order 23): -72.5,13.8 -72.5,17.5 -72.7,17.7 -72.7,18.1 -71.3,18.1 -71.1,17.9 -71.1,13.8
REG18 on BOT "REG18_L06_P058" (solid, pour order 58): -69.4,25.8 -69.4,24.1 -73.6,24.1 -73.6,25.8
"VDD BQ" on BOT "VDD_BQ_L06_P057" (solid, pour order 57): -91.4,15 -91.4,18.6 -90.7,18.6 -90.7,16.7 -90.2,16.2 -89.9,16.2 -89.9,15
PACK- on BOT "PACK-_L06_P024" (solid, pour order 24): -7.875,33.4 -7.875,35.55 -9.825,37.5 -12.5,37.5 -12.5,33.4
PACK- on BOT "PACK-_L06_P056" (solid, pour order 56): -7.65,13.3 -7.65,15.6 -4,15.6 -4,13.3
NetC39_2 on BOT "NETC39_2_L06_P048" (solid, pour order 48): -7.65,13.3 -4,13.3 -4,11.55 -4.475,11.075 -7.65,11.075
PACK on BOT "PACK_L06_P047" (solid, remove dead copper, pour order 47): -71.9,5.4 -71.9,15.6 -77.1,15.6 -81.7,11 -81.7,5.4
LD on BOT "LD_L06_P046" (solid, pour order 46): -71.9,5.4 -71.9,15.6 -62,15.6 -62,5.4
PACK+ on BOT "PACK+_L06_P045" (solid, pour order 45): -81.8,5.4 -62,5.4 -62,0 -81.8,0
NetC13_2 on BOT "NETC13_2_L06_P042" (solid, pour order 42): -49.81,35.19 -30.41,35.19 -30.5,35.28 -30.5,38 -49.798,38
NetC13_2 on BOT "NETC13_2_L06_P041" (solid, remove dead copper, pour order 41): -67.6,24 -49.8,24 -49.8,38.2 -67.6,38.2
NetC13_2 on BOT "NETC13_2_L06_P040" (solid, pour order 40): -24,38 -30.6,38 -30.6,18.9 -27.4,18.9 -26.8,19.5 -26.8,21.3 -24,24.1
NetR12_1 on BOT "NETR12_1_L06_P039" (solid, pour order 39): -21,22.5 -22.6,24.1 -24,24.1 -24,38 -20.2,38 -17.316,35.116 -17.3,28.6 -9.1,28.6 -9.1,26.9 -9.1,22.5
NetD13_K on BOT "NETD13_K_L06_P038" (solid, pour order 38): -21,22.5 -9.1,22.5 -9.1,18.5 -15,12.6 -17,12.6 -17,14.8 -21,18.8
GND_BMS on BOT "GND_BMS_L06_P036" (solid, pour order 36): -49.81,35.19 -30.41,35.19 -30.41,19.49 -49.81,19.49
NetD12_K on BOT "NETD12_K_L06_P026" (solid, pour order 26): -55.4,0 -62,0 -62,4.5 -55.4,4.5
NetD10_K on BOT "NETD10_K_L06_P027" (solid, pour order 27): -55.4,4.5 -55.4,0 -48.1,0 -48.1,4.5
DSG on BOT "DSG_L06_P035" (solid, pour order 35): -48,9 -48,4.5 -62,4.5 -62,9
G_DSG on BOT "G_DSG_L06_P034" (solid, pour order 34): -48,14 -48,19.1 -62,19.1 -62,14
NetR4_1 on BOT "NETR4_1_L06_P033" (solid, pour order 33): -48,9 -48,14 -62,14 -62,9
NetQ1_D on BOT "NETQ1_D_L06_P031" (solid, remove dead copper, pour order 31): -25.5,0 -25.5,19 -48.1,19 -48.1,0
PACK- on TOP "PACK-_L01_P000" (solid, pour order 0): -74.8,36.5 -71.4,36.5 -69.9,38 -19.9,38 -17.208,35.308 -17.208,33.3 0,33.3 0,42 -74.8,42
GND_BMS on TOP "GND_BMS_L01_P087" (solid, pour order 87): -96,36.5 -79.6,36.5 -76.2,36.5 -76.2,42 -96,42
GND_BMS on TOP "GND_BMS_L01_P083" (solid, pour order 83): -105,33 -96,33 -96,42 -105,42
NetC38_2 on TOP "NETC38_2_L01_P005" (solid, pour order 5): 0,21.7 -3.8,21.7 -3.8,27.4 -5.45,29.05 -16.8,29.05 -16.8,33.3 0,33.3
NetC39_2 on TOP "NETC39_2_L01_P082" (solid, pour order 82): -4.4,9.4 0,9.4 0,21.7 -3.8,21.7 -3.8,13.9 -4.4,13.3
BAT+ on TOP "BAT+_L01_P007" (solid, pour order 7): -13.7,9.4 -13.677,9.423 -13.677,12.6 -21.996,12.6 -21.996,9.4
GND_BMS on TOP "GND_BMS_L01_P079" (solid, pour order 79): -8.015,7.485 -8.015,9.385 -8,9.4 0,9.4 0,7.5
NetC39_2 on TOP "NETC39_2_L01_P076" (solid, pour order 76): -13.7,13.3 -4.4,13.3 -4.4,9.4 -13.7,9.4
PACK- on TOP "PACK-_L01_P075" (solid, pour order 75): -13.7,13.3 -4.4,13.3 -3.8,13.9 -3.8,17.5 -13.677,17.5
PACK+ on TOP "PACK+_L01_P074" (solid, pour order 74): -25.5,11.1 -21,11.1 -21,20.5 -25.5,20.5
NetC3_2 on TOP "NETC3_2_L01_P073" (solid, pour order 73): -23.6,11.8 -23.6,8.8 -22.2,8.8 -22.2,11.8
BAT+ on TOP "BAT+_L01_P006" (solid, pour order 6): -9.7,17.5 -6.2,17.5 -6.2,28.9 -9.7,28.9
BAT+ on TOP "BAT+_L01_P072" (solid, pour order 72): -8.015,5 -8,5.015 -8,9.4 -25.5,9.4 -25.5,0 -18,0 -18,5
"BAT+ C" on TOP "TOP-BAT+ C" (solid, pour order 71): 0,0 0,7.5 -8,7.5 -8.015,7.485 -8.015,5 -18,5 -18,0
VDD on TOP "VDD_L01_P070" (solid, pour order 70): -75.5,9.7 -75.5,8.3 -76.9,8.3 -77,8.4 -79.1,8.4 -79.1,8.9 -77.6,8.9 -76.8,9.7
VCORE on TOP "VCORE_L01_P069" (solid, pour order 69): -80,5.5 -80,2.2 -79.6,1.8 -78.6,1.8 -78.6,4.4 -79.7,5.5
VDD on TOP "VDD_L01_P066" (solid, pour order 66): -73,28.1 -73,26.9 -69.6,26.9 -69.6,28.7 -70.6,28.7 -71.2,28.1
REG25 on TOP "REG25_L01_P062" (solid, pour order 62): -73,28.1 -71.2,28.1 -70.6,28.7 -69.6,28.7 -69.6,30.1 -70.7,30.1 -72,28.8 -73,28.8
VDD on TOP "VDD_L01_P055" (solid, pour order 55): -69.1,14.3 -69.1,12.8 -66,12.8 -66,13.7 -67.6,13.7 -68.2,14.3
5V1 on TOP "5V1_L01_P054" (solid, pour order 54): -67.8,16 -69.1,16 -69.1,14.3 -68.2,14.3 -67.6,13.7 -66,13.7 -66,14.5 -66.2,14.7 -67.4,14.7 -67.8,15.1
GND_BMS on TOP "GND_BMS_L01_P053" (solid, pour order 53): -67.8,15.1 -67.4,14.7 -66.2,14.7 -66,14.5 -66,12.8 -63.5,12.8 -63.5,16 -67.8,16
NetC13_2 on TOP "NETC13_2_L01_P052" (solid, pour order 52): -49.81,33.79 -41.21,33.79 -41.21,35.19 -30.41,35.19 -30.41,37.49 -30.41,38 -49.799,38
NetC13_2 on TOP "NETC13_2_L01_P051" (solid, remove dead copper, pour order 51): -67.6,24 -49.8,24 -49.8,38 -67.6,38
NetR12_1 on TOP "NETR12_1_L01_P050" (solid, remove dead copper, pour order 50): -21,22.5 -22.6,24.1 -24,24.1 -24,38 -19.9,38 -17.186,35.286 -17.214,29 -9.7,29 -9.7,27.8 -9.7,22.5
NetC13_2 on TOP "NETC13_2_L01_P049" (solid, pour order 49): -24,38 -30.6,38 -30.6,18.9 -27.4,18.9 -26.8,19.5 -26.8,21.3 -24,24.1
NetD13_K on TOP "NETD13_K_L01_P032" (solid, pour order 32): -21,22.5 -9.7,22.5 -9.7,17.5 -13.677,17.5 -13.677,12.6 -21,12.6
"VIN 5V1" on TOP "VIN_5V1_L01_P010" (solid, pour order 10): -48.41,33.79 -45.81,33.79 -45.81,31.49 -44.71,30.39 -44.71,28.19 -45.754,28.19 -45.754,29.734 -46.41,30.39 -48.41,30.39
GND_BMS on TOP "TOP-GND_BMS" (solid, pour order 11): -49.81,19.34 -30.31,19.34 -30.31,25.99 -30.41,26.09 -43.01,26.09 -43.01,29.79 -42.71,30.09 -41.21,30.09 -41.21,33.79 -45.81,33.79 -45.81,31.49 -44.71,30.39 -44.71,28.19 -45.754,28.19 -45.754,29.734 -46.41,30.39 -48.41,30.39 -48.41,33.79 -49.81,33.79 -49.81,22.39
NetC40_1 on TOP "NETC40_1_L01_P028" (solid, pour order 28): -45.61,24.49 -45.61,22.89 -46.11,22.39 -46.11,20.99 -44.71,20.99 -44.71,24.49
"SW 5V1" on TOP "SW_5V1_L01_P029" (solid, pour order 29): -44.71,20.99 -43.31,20.99 -43.31,24.49 -44.71,24.49
5V1 on TOP "5V1_L01_P030" (solid, pour order 30): -41.21,35.19 -30.41,35.19 -30.41,26.09 -43.01,26.09 -43.01,29.79 -42.71,30.09 -41.21,30.09
NetD12_K on TOP "NETD12_K_L01_P014" (solid, pour order 14): -55.4,0 -62,0 -62,4.5 -55.4,4.5
NetD10_K on TOP "NETD10_K_L01_P015" (solid, pour order 15): -55.4,4.5 -55.4,0 -48.1,0 -48.1,4.5
DSG on TOP "DSG_L01_P025" (solid, pour order 25): -48,9 -48,4.5 -62,4.5 -62,9
G_DSG on TOP "G_DSG_L01_P022" (solid, pour order 22): -48,14 -48,19.1 -62,19.1 -62,14
NetR4_1 on TOP "NETR4_1_L01_P017" (solid, pour order 17): -48,9 -48,14 -62,14 -62,9
NetQ1_D on TOP "NETQ1_D_L01_P016" (solid, pour order 16): -25.5,0 -25.5,19 -48.1,19 -48.1,0
PACK- on GND TOP "PACK-_L02_P043" (solid, pour order 43): -74.8,36.5 -71.4,36.5 -69.9,38 -19.9,38 -17.208,35.308 -17.208,33.3 0,33.3 0,42 -74.8,42
"BAT+ C" on GND TOP "IN1-BAT+ C" (solid, pour order 68): 0,0 0,7.5 -8,7.5 -8.015,7.485 -8.015,5 -18,5 -18,0
GND_BMS on GND TOP "GND_BMS_L02_P088" (solid, pour order 88): -105,42 0,42 0,0 -105,0
PACK- on GND BOT "PACK-_L05_P044" (solid, pour order 44): -74.8,36.5 -71.4,36.5 -69.9,38 -19.9,38 -17.208,35.308 -17.208,33.3 0,33.3 0,42 -74.8,42
NetC38_2 on GND BOT "NETC38_2_L05_P065" (solid, pour order 65): 0,21.7 -4.8,21.7 -4.8,28.4 -5.45,29.05 -16.8,29.05 -16.8,33.3 0,33.3
"BAT+ C" on GND BOT "IN2-BAT+ C" (solid, pour order 67): 0,0 0,7.5 -8,7.5 -8.015,7.485 -8.015,5 -18,5 -18,0
BAT+ on GND BOT "BAT+_L05_P081" (solid, pour order 81): -18,5 -18,9.6 -9.609,17.991 -9.609,26.491 -9.6,26.5 -5,26.5 -5,21.5 0,21.5 0,7.5 -8,7.5 -8,5.015 -8.015,5
GND_BMS on GND BOT "GND_BMS_L05_P089" (solid, pour order 89): -105,42 0,42 0,0 -105,0
"BAT+ C" on GND IN "TOP-BAT+ C" (solid, pour order 95): 0,0 0,7.5 -8,7.5 -8.015,7.485 -8.015,5 -18,5 -18,0
GND_BMS on GND IN "GND_BMS_L04_P093" (solid, pour order 93): -105,42 -105,0 0,0 0,42
"BAT+ C" on IN "TOP-BAT+ C" (solid, pour order 94): 0,0 0,7.5 -8,7.5 -8.015,7.485 -8.015,5 -18,5 -18,0

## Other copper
TOP:
  rectangle net GND_BMS: -104,33 -96,41
BOT:
  rectangle net "BAT+ C": -7.5,0.5 -0.5,7.5

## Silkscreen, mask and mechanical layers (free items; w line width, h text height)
Top Overlay:
  text "BAT-" at -94.95,38.05 h1
  text "EN" at -50.85,34.05 h0.75
  text "BMS v1 / Jan. 2026" at -92.3,31.1 h0.75
  text "PACK-" at -63.95,24.85 h1
  text "PACK+" at -25.95,24.85 h1
  text "PGOOD" at -48.85,22.85 h0.75 r90
  text "5VBMS" at -74.55,16.95 h0.75
  text "DOUT" at -49.15,14.15 h0.75
  text "GDSG" at -45.75,14.15 h0.75
  text "3V3" at -66.25,8.25 h0.75
  text "SCL" at -93.65,6.05 h0.75 r90
  text "SDA" at -96.15,5.95 h0.75 r90
  text "GND" at -91.25,5.95 h0.75 r90
  text "COUT" at -49.65,4.95 h0.75
  text "GCHG" at -45.05,4.95 h0.75
  text "MCU" at -88.85,4.05 h0.75
  text "FUSE" at -24.65,1.95 h0.75
Bottom Overlay:
  text "BAT+" at -2.536,7.85 h1
Board:
  the board outline again, w0.2

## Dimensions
-105,0 to -106,21 on Dimensions
-105,0 to -105,42 on Dimensions
0,0.5 to -105,0.5 on Dimensions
